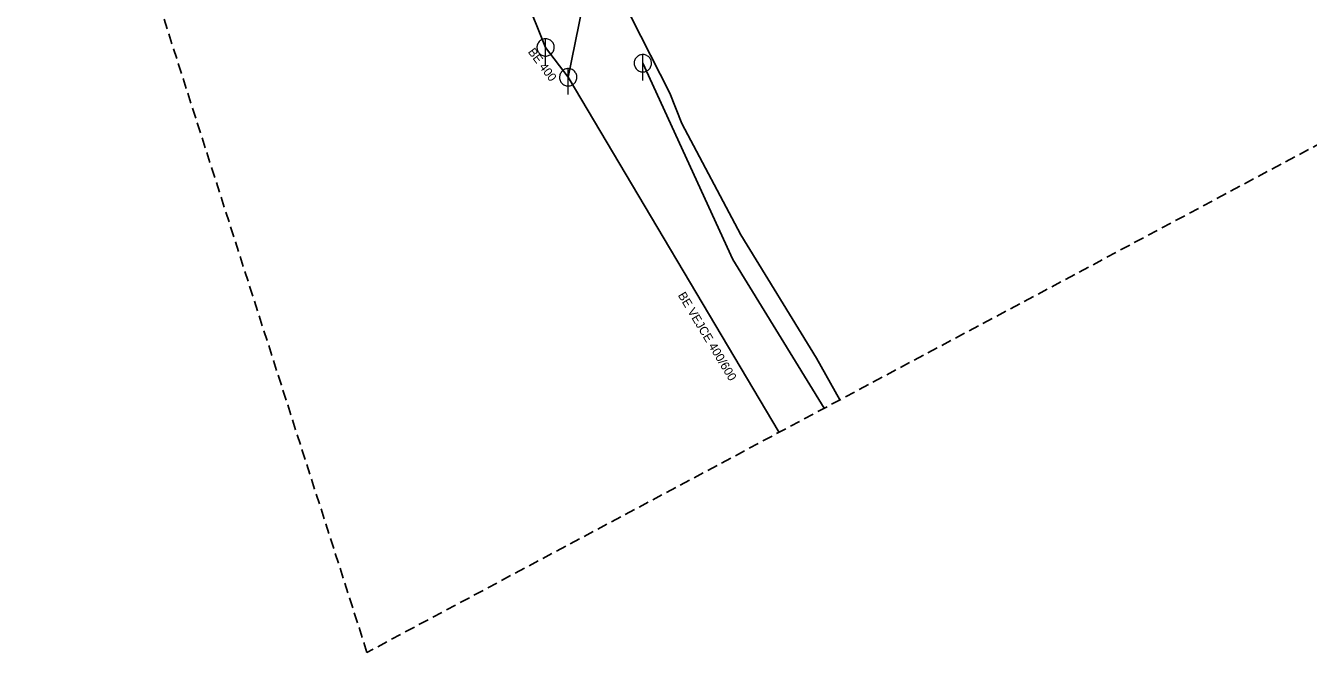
# Model space of a CAD drawing. Extents: x -779496 to -779026, y -977086 to -976624.
# Drawn here: x -779496.1 to -779348.1, y -977086.5 to -977014.1 of the extents above; entities that cross this region are included whole.
import ezdxf

# ---------------------------------------------------------------- set-up
doc = ezdxf.new("R2010")
doc.units = 0
doc.header["$LTSCALE"] = 0.4
doc.linetypes.add('MEDIUM_DASHED', pattern=[4.5, 3, -1.5])
for name, color, linetype, lineweight in [('1', 7, 'MEDIUM_DASHED', 25), ('14', 7, 'Continuous', 13), ('17', 7, 'Continuous', 25), ('22', 7, 'Continuous', 13)]:
    doc.layers.add(name, color=color, linetype=linetype, lineweight=lineweight)

msp = doc.modelspace()

# ---------------------------------------------------------------- linework, layer by layer
at = {"layer": '1'}
msp.add_lwpolyline([(-779144.045, -976624.23), (-779025.876, -976692.559), (-779211.57, -976955.425), (-779456.75, -977086.455), (-779496.14, -976963.463), (-779320.896, -976797.866)], close=True, dxfattribs=at)
at = {"layer": '14', "lineweight": 25}
for p, q in [((-779446.634, -976990.353), (-779436.14, -977016.59)), ((-779436.14, -977016.59), (-779433.53, -977020.039))]:
    msp.add_line(p, q, dxfattribs=at)
for points in [[(-779431.048, -977007.721), (-779433.53, -977020.039), (-779409.204, -977061.045)], [(-779424.921, -977018.414), (-779414.515, -977041.083), (-779403.979, -977058.253)]]:
    msp.add_lwpolyline(points, dxfattribs=at)
at = {"layer": '17'}
msp.add_lwpolyline([(-779431.872, -977001.993), (-779421.818, -977021.866), (-779420.403, -977025.364), (-779413.614, -977038.243), (-779404.897, -977052.484), (-779402.2, -977057.302)], dxfattribs=at)
at = {"layer": '22'}
for p, q in [((-779436.14, -977018.59), (-779436.139, -977015.59)), ((-779424.921, -977020.414), (-779424.92, -977017.414)), ((-779433.53, -977022.039), (-779433.529, -977019.039))]:
    msp.add_line(p, q, dxfattribs=at)
for points in [[(-779435.14, -977016.59), (-779435.145, -977016.481), (-779435.163, -977016.373), (-779435.193, -977016.267), (-779435.233, -977016.166), (-779435.285, -977016.069), (-779435.347, -977015.979), (-779435.419, -977015.896), (-779435.499, -977015.822), (-779435.587, -977015.756), (-779435.681, -977015.701), (-779435.781, -977015.656), (-779435.886, -977015.623), (-779435.993, -977015.601), (-779436.102, -977015.591), (-779436.212, -977015.593), (-779436.32, -977015.607), (-779436.427, -977015.632), (-779436.53, -977015.669), (-779436.628, -977015.718), (-779436.72, -977015.776), (-779436.806, -977015.845), (-779436.883, -977015.922), (-779436.952, -977016.008), (-779437.011, -977016.1), (-779437.059, -977016.198), (-779437.096, -977016.301), (-779437.122, -977016.408), (-779437.136, -977016.516), (-779437.139, -977016.626), (-779437.129, -977016.735), (-779437.108, -977016.842), (-779437.074, -977016.946), (-779437.03, -977017.046), (-779436.975, -977017.141), (-779436.909, -977017.229), (-779436.835, -977017.309), (-779436.752, -977017.381), (-779436.662, -977017.443), (-779436.566, -977017.495), (-779436.464, -977017.536), (-779436.359, -977017.566), (-779436.251, -977017.584), (-779436.141, -977017.59), (-779436.032, -977017.584), (-779435.924, -977017.566), (-779435.819, -977017.537), (-779435.717, -977017.496), (-779435.62, -977017.444), (-779435.53, -977017.382), (-779435.447, -977017.311), (-779435.372, -977017.231), (-779435.307, -977017.143), (-779435.251, -977017.049), (-779435.207, -977016.949), (-779435.173, -977016.845), (-779435.151, -977016.737), (-779435.141, -977016.628)], [(-779423.921, -977018.414), (-779423.926, -977018.305), (-779423.944, -977018.197), (-779423.974, -977018.091), (-779424.014, -977017.99), (-779424.066, -977017.893), (-779424.128, -977017.803), (-779424.2, -977017.72), (-779424.28, -977017.646), (-779424.368, -977017.58), (-779424.462, -977017.525), (-779424.562, -977017.48), (-779424.667, -977017.447), (-779424.774, -977017.425), (-779424.883, -977017.415), (-779424.993, -977017.417), (-779425.101, -977017.431), (-779425.208, -977017.456), (-779425.311, -977017.493), (-779425.409, -977017.542), (-779425.501, -977017.6), (-779425.587, -977017.669), (-779425.664, -977017.746), (-779425.733, -977017.832), (-779425.792, -977017.924), (-779425.84, -977018.022), (-779425.877, -977018.125), (-779425.903, -977018.232), (-779425.917, -977018.34), (-779425.92, -977018.45), (-779425.91, -977018.559), (-779425.889, -977018.666), (-779425.855, -977018.77), (-779425.811, -977018.87), (-779425.756, -977018.965), (-779425.69, -977019.053), (-779425.616, -977019.133), (-779425.533, -977019.205), (-779425.443, -977019.267), (-779425.347, -977019.319), (-779425.245, -977019.36), (-779425.14, -977019.39), (-779425.032, -977019.408), (-779424.922, -977019.414), (-779424.813, -977019.408), (-779424.705, -977019.39), (-779424.6, -977019.361), (-779424.498, -977019.32), (-779424.401, -977019.268), (-779424.311, -977019.206), (-779424.228, -977019.135), (-779424.153, -977019.055), (-779424.088, -977018.967), (-779424.032, -977018.873), (-779423.988, -977018.773), (-779423.954, -977018.669), (-779423.932, -977018.561), (-779423.922, -977018.452)], [(-779432.53, -977020.039), (-779432.535, -977019.93), (-779432.553, -977019.822), (-779432.583, -977019.716), (-779432.623, -977019.615), (-779432.675, -977019.518), (-779432.737, -977019.428), (-779432.809, -977019.345), (-779432.889, -977019.271), (-779432.977, -977019.205), (-779433.071, -977019.15), (-779433.171, -977019.105), (-779433.276, -977019.072), (-779433.383, -977019.05), (-779433.492, -977019.04), (-779433.602, -977019.042), (-779433.71, -977019.056), (-779433.817, -977019.081), (-779433.92, -977019.118), (-779434.018, -977019.167), (-779434.11, -977019.225), (-779434.196, -977019.294), (-779434.273, -977019.371), (-779434.342, -977019.457), (-779434.401, -977019.549), (-779434.449, -977019.647), (-779434.486, -977019.75), (-779434.512, -977019.857), (-779434.526, -977019.965), (-779434.529, -977020.075), (-779434.519, -977020.184), (-779434.498, -977020.291), (-779434.464, -977020.395), (-779434.42, -977020.495), (-779434.365, -977020.59), (-779434.299, -977020.678), (-779434.225, -977020.758), (-779434.142, -977020.83), (-779434.052, -977020.892), (-779433.956, -977020.944), (-779433.854, -977020.985), (-779433.749, -977021.015), (-779433.641, -977021.033), (-779433.531, -977021.039), (-779433.422, -977021.033), (-779433.314, -977021.015), (-779433.209, -977020.986), (-779433.107, -977020.945), (-779433.01, -977020.893), (-779432.92, -977020.831), (-779432.837, -977020.76), (-779432.762, -977020.68), (-779432.697, -977020.592), (-779432.641, -977020.498), (-779432.597, -977020.398), (-779432.563, -977020.294), (-779432.541, -977020.186), (-779432.531, -977020.077)]]:
    msp.add_lwpolyline(points, close=True, dxfattribs=at)

# ---------------------------------------------------------------- texts
at = {"layer": '1'}
for s, rotation, p in [('BE 400', 307, (-779438.227, -977017.12)), ('BE VEJCE 400/600', 301, (-779420.909, -977045.203))]:
    msp.add_text(s, height=1, rotation=rotation, dxfattribs=at).set_placement(p)

doc.saveas('drawing.dxf')
